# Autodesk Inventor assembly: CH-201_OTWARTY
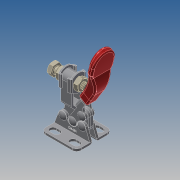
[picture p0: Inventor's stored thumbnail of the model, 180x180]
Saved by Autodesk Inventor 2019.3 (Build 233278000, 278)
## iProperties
Company: Î¢ÈíÖÐ¹ú
Created: 2012-09
Part Number: CH-201_OTWARTY
Material: Ogólny
Description: STEP AP203
Document SubType Name: Assembly
Designer: CADENGINEERING4
Sending System: SolidWorks 2010
Preprocessor: SwSTEP 2.0
Title: CH-201.STEP
Author: Î¢ÈíÓÃ»§
Revision Number: ÈÎºÎ
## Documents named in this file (9)
- E:\STRONA\Horizontal toggle clamp\CH-201\CH-201_OTWARTY.iam
- E:\STRONA\Horizontal toggle clamp\CH-201\CH-201-02 U-BAR.ipt
- E:\STRONA\Horizontal toggle clamp\CH-201\CH-FW-080.ipt
- E:\STRONA\Horizontal toggle clamp\CH-201\CH-201-A-06.ipt
- E:\STRONA\Horizontal toggle clamp\CH-201\CH-201-A-04.ipt
- E:\STRONA\Horizontal toggle clamp\CH-201\CH-201-03 HANDLE.iam
- E:\STRONA\Horizontal toggle clamp\CH-201\M4 Nut.ipt
- E:\STRONA\Horizontal toggle clamp\CH-201\CH-SA-042007 SPINDLE SUPPLIED.ipt
- E:\STRONA\Horizontal toggle clamp\CH-201\CH-201-01 FLANGED BASE.ipt
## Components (14 placed, 14 different names)
1. CH-201-02 U-BAR_1 — Zestawiające:23, Zestawiające:24, Zestawiające:25, Zestawiające:26, Równoległe:3, Zestawiające:27, Zestawiające:28
2. CH-FW-080_2 — Zestawiające:20, Zestawiające:21, Zestawiające:24, Równoległe:2
3. CH-201-A-06_3 — Zestawiające:6, Zestawiające:12
4. CH-201-A-04_4 — Zestawiające:1, Zestawiające:2, Zestawiające:3, Zestawiające:9, Zestawiające:10, Zestawiające:11
5. CH-201-03 HANDLE_5 [sub-assembly] — Zestawiające:6, Zestawiające:10, Zestawiające:11, Zestawiające:13, Zestawiające:14, Przejściowe:1
6. M4 Nut_6 — Zestawiające:17, Zestawiające:21
7. CH-SA-042007 SPINDLE SUPPLIED_7 — Zestawiające:17, Równoległe:1, Zestawiające:18, Zestawiające:19, Zestawiające:20, Zestawiające:27
8. CH-201-01 FLANGED BASE_8 — Zestawiające:4, Zestawiające:5, Zestawiające:8, Zestawiające:15, Zestawiające:16, Zestawiające:26, Przejściowe:1
9. M4 Nut_9 — Równoległe:1, Zestawiające:18, Zestawiające:22
10. CH-201-A-04_10 — Zestawiające:1, Zestawiające:2, Zestawiające:3, Zestawiające:8, Zestawiające:12
11. CH-201-A-06_11 — Zestawiające:4, Zestawiające:5, Zestawiające:9
12. CH-201-A-06_12 — Zestawiające:15, Zestawiające:16, Zestawiające:25
13. CH-FW-080_13 — Zestawiające:19, Zestawiające:22, Zestawiające:23, Równoległe:2, Równoległe:3
14. CH-201-A-06_14 — Zestawiające:13, Zestawiające:14, Zestawiające:28
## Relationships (31: Mate 27, Flush 3, Transitional 1)
- Zestawiające:1 [Mate]: CH-201-A-04_4 ↔ CH-201-A-04_10
- Zestawiające:2 [Mate]: CH-201-A-04_4 ↔ CH-201-A-04_10
- Zestawiające:3 [Mate]: CH-201-A-04_4 ↔ CH-201-A-04_10
- Zestawiające:4 [Mate]: CH-201-01 FLANGED BASE_8 ↔ CH-201-A-06_11
- Zestawiające:5 [Mate]: CH-201-01 FLANGED BASE_8 ↔ CH-201-A-06_11
- Zestawiające:6 [Mate]: CH-201-A-06_3 ↔ CH-201-03 HANDLE_5
- Zestawiające:8 [Mate]: CH-201-01 FLANGED BASE_8 ↔ CH-201-A-04_10
- Zestawiające:9 [Mate]: CH-201-A-04_4 ↔ CH-201-A-06_11
- Zestawiające:10 [Mate]: CH-201-A-04_4 ↔ CH-201-03 HANDLE_5
- Zestawiające:11 [Mate]: CH-201-A-04_4 ↔ CH-201-03 HANDLE_5
- Zestawiające:12 [Mate]: CH-201-A-06_3 ↔ CH-201-A-04_10
- Zestawiające:13 [Mate]: CH-201-03 HANDLE_5 ↔ CH-201-A-06_14
- Zestawiające:14 [Mate]: CH-201-03 HANDLE_5 ↔ CH-201-A-06_14
- Zestawiające:15 [Mate]: CH-201-01 FLANGED BASE_8 ↔ CH-201-A-06_12
- Zestawiające:16 [Mate]: CH-201-01 FLANGED BASE_8 ↔ CH-201-A-06_12
- Zestawiające:17 [Mate]: M4 Nut_6 ↔ CH-SA-042007 SPINDLE SUPPLIED_7
- Równoległe:1 [Flush]: CH-SA-042007 SPINDLE SUPPLIED_7 ↔ M4 Nut_9
- Zestawiające:18 [Mate]: CH-SA-042007 SPINDLE SUPPLIED_7 ↔ M4 Nut_9
- Zestawiające:19 [Mate]: CH-SA-042007 SPINDLE SUPPLIED_7 ↔ CH-FW-080_13
- Zestawiające:20 [Mate]: CH-FW-080_2 ↔ CH-SA-042007 SPINDLE SUPPLIED_7
- Zestawiające:21 [Mate]: CH-FW-080_2 ↔ M4 Nut_6
- Zestawiające:22 [Mate]: M4 Nut_9 ↔ CH-FW-080_13
- Zestawiające:23 [Mate]: CH-201-02 U-BAR_1 ↔ CH-FW-080_13
- Zestawiające:24 [Mate]: CH-201-02 U-BAR_1 ↔ CH-FW-080_2
- Równoległe:2 [Flush]: CH-FW-080_2 ↔ CH-FW-080_13
- Zestawiające:25 [Mate]: CH-201-02 U-BAR_1 ↔ CH-201-A-06_12
- Zestawiające:26 [Mate]: CH-201-02 U-BAR_1 ↔ CH-201-01 FLANGED BASE_8
- Równoległe:3 [Flush]: CH-201-02 U-BAR_1 ↔ CH-FW-080_13
- Zestawiające:27 [Mate]: CH-201-02 U-BAR_1 ↔ CH-SA-042007 SPINDLE SUPPLIED_7
- Zestawiające:28 [Mate]: CH-201-02 U-BAR_1 ↔ CH-201-A-06_14
- Przejściowe:1 [Transitional]: CH-201-03 HANDLE_5 ↔ CH-201-01 FLANGED BASE_8
